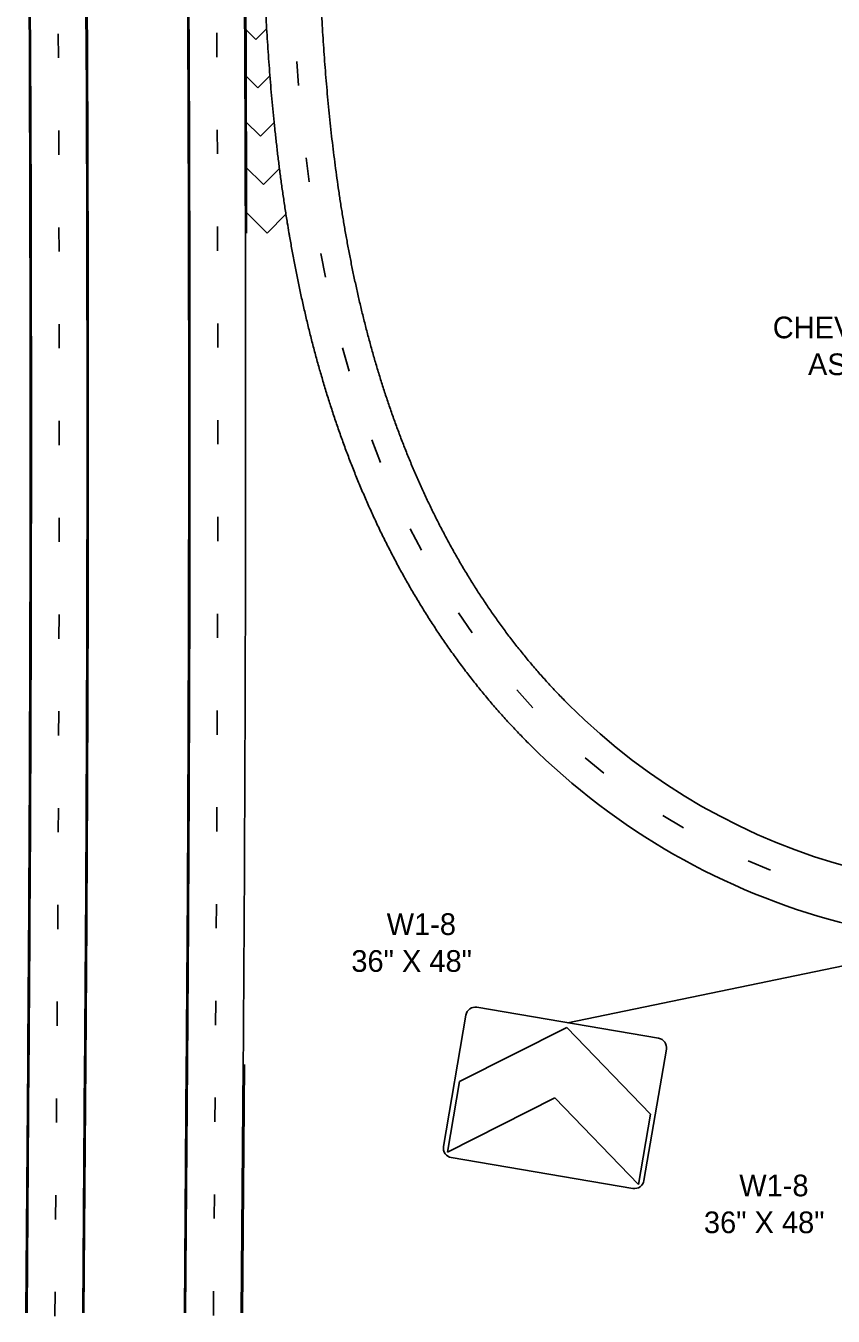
# Model space of a CAD drawing. Extents: x 582908 to 586040, y 1530940 to 1532988.
# Drawn here: x 584487 to 585009, y 1531179 to 1532013 of the extents above; entities that cross this region are included whole.
import ezdxf

# ---------------------------------------------------------------- set-up
doc = ezdxf.new("R2010")
doc.units = 0
for name, color, linetype in [('LeaderLine_dp', 7, 'Continuous'), ('NonPlottingEle_dp', 7, 'Continuous'), ('PavtMisc_ep', 7, 'Continuous'), ('PMStripe18W', 7, 'Continuous'), ('PMStripe6W', 7, 'Continuous'), ('PMStripe6W(10-30)', 7, 'Continuous'), ('PMStripe6Y', 7, 'Continuous'), ('PMStripe8W', 7, 'Continuous'), ('SignPanel', 7, 'Continuous'), ('TextLabel', 7, 'Continuous')]:
    doc.layers.add(name, color=color, linetype=linetype)

msp = doc.modelspace()

# ---------------------------------------------------------------- linework, layer by layer
at = {"layer": 'LeaderLine_dp'}
msp.add_line((585049.11, 1531412.72), (584837.21, 1531368.99), dxfattribs=at)
at = {"layer": 'NonPlottingEle_dp'}
for p, q in [((584488.37, 1532305.68), (584489.76, 1531989.04)), ((584628.22, 1532306.3), (584629.61, 1531989.65)), ((584488.69, 1531343.06), (584487.46, 1531181.72)), ((584628.53, 1531341.99), (584627.3, 1531181.72))]:
    msp.add_line(p, q, dxfattribs=at)
for radius, start in [(53646.05, 359.560511), (53785.89, 0.132453)]:
    msp.add_arc((530844.22, 1531754.55), radius, start, 0.250444, dxfattribs=at)
at = {"layer": 'PavtMisc_ep'}
for p, q in [((584525.87, 1532305.84), (584527.26, 1531989.2)), ((584590.72, 1532306.13), (584592.11, 1531989.49)), ((584526.19, 1531342.77), (584524.96, 1531181.72)), ((584591.03, 1531342.27), (584589.8, 1531181.72))]:
    msp.add_line(p, q, dxfattribs=at)
for radius in [53683.55, 53748.39]:
    msp.add_arc((530844.22, 1531754.55), radius, 359.560511, 0.250444, dxfattribs=at)
at = {"layer": 'PMStripe18W'}
for p, q in [((584636, 1532003.89), (584628.69, 1532011.14)), ((584636, 1532003.89), (584642.84, 1532010.8)), ((584637.26, 1531972.65), (584628.82, 1531981.01)), ((584637.26, 1531972.65), (584645.01, 1531980.47)), ((584638.85, 1531941.4), (584628.97, 1531951.2)), ((584638.85, 1531941.4), (584647.77, 1531950.4)), ((584640.83, 1531910.16), (584629.07, 1531921.82)), ((584640.83, 1531910.16), (584651.2, 1531920.62)), ((584643.25, 1531878.92), (584629.16, 1531892.9)), ((584643.25, 1531878.92), (584655.34, 1531891.12))]:
    msp.add_line(p, q, dxfattribs=at)
at = {"layer": 'PMStripe6W'}
for p, q in [((584489.16, 1532305.68), (584490.54, 1531989.04)), ((584489.47, 1531343.05), (584488.24, 1531181.72)), ((584627.75, 1531341.99), (584626.52, 1531181.72))]:
    msp.add_line(p, q, dxfattribs=at)
for centre, radius, start, end in [((585125.59, 1531862.24), 407.03, 225.07112, 46.1803), ((530844.22, 1531754.55), 53646.83, 359.560511, 0.250444), ((530844.22, 1531754.55), 53785.11, 359.560511, 0.132453)]:
    msp.add_arc(centre, radius, start, end, dxfattribs=at)
msp.add_spline([(584674.06, 1532160.86), (584674.21, 1532152.42), (584674.36, 1532143.97), (584674.51, 1532135.53), (584674.67, 1532127.08), (584674.84, 1532118.64), (584675.03, 1532110.19), (584675.22, 1532101.75), (584675.44, 1532093.3), (584675.67, 1532084.86), (584675.93, 1532076.41), (584676.2, 1532067.97), (584676.51, 1532059.52), (584676.84, 1532051.08), (584677.2, 1532042.64), (584677.6, 1532034.2), (584678.03, 1532025.76), (584678.5, 1532017.33), (584679.01, 1532008.89), (584679.57, 1532000.46), (584680.16, 1531992.03), (584680.81, 1531983.61), (584681.5, 1531975.18), (584682.25, 1531966.77), (584683.05, 1531958.35), (584683.91, 1531949.95), (584684.83, 1531941.54), (584685.81, 1531933.15), (584686.85, 1531924.76), (584687.96, 1531916.38), (584689.14, 1531908.01), (584690.38, 1531899.65), (584691.7, 1531891.3), (584693.1, 1531882.97), (584694.57, 1531874.64), (584696.12, 1531866.33), (584697.76, 1531858.04), (584699.47, 1531849.76), (584701.28, 1531841.5), (584703.17, 1531833.26), (584705.15, 1531825.04), (584707.22, 1531816.85), (584709.39, 1531808.67), (584711.66, 1531800.53), (584714.02, 1531792.41), (584716.48, 1531784.32), (584719.05, 1531776.26), (584721.72, 1531768.24), (584724.49, 1531760.25), (584727.37, 1531752.3), (584730.37, 1531744.39), (584733.47, 1531736.52), (584736.68, 1531728.7), (584740.01, 1531720.93), (584743.46, 1531713.2), (584747.02, 1531705.53), (584750.7, 1531697.91), (584754.5, 1531690.36), (584758.42, 1531682.86), (584762.46, 1531675.43), (584766.63, 1531668.07), (584770.91, 1531660.78), (584775.33, 1531653.56), (584779.86, 1531646.42), (584784.53, 1531639.36), (584789.32, 1531632.39), (584794.23, 1531625.5), (584799.28, 1531618.71), (584804.45, 1531612.01), (584809.74, 1531605.42), (584815.17, 1531598.92), (584820.72, 1531592.54), (584826.4, 1531586.26), (584832.2, 1531580.1), (584838.12, 1531574.07)], degree=3, dxfattribs=at)
at = {"layer": 'PMStripe6W(10-30)'}
for p, q in [((584508.43, 1532007.6), (584508.5, 1531991.98)), ((584610.78, 1532008.11), (584610.84, 1531992.49)), ((584662.32, 1531989.69), (584663.56, 1531974.11)), ((584611.03, 1531945.61), (584611.08, 1531929.99)), ((584508.68, 1531945.1), (584508.74, 1531929.48)), ((584668.4, 1531927.49), (584670.42, 1531912)), ((584508.87, 1531882.6), (584508.9, 1531866.98)), ((584611.21, 1531883.11), (584611.25, 1531867.49)), ((584677.94, 1531865.73), (584680.98, 1531850.41)), ((584611.32, 1531820.61), (584611.34, 1531804.99)), ((584508.98, 1531820.1), (584509, 1531804.48)), ((584691.82, 1531804.81), (584696.06, 1531789.77)), ((584509.02, 1531757.6), (584509.02, 1531741.98)), ((584611.36, 1531758.11), (584611.36, 1531742.49)), ((584710.81, 1531745.29), (584716.44, 1531730.71)), ((584611.33, 1531695.61), (584611.31, 1531679.99)), ((584508.99, 1531695.1), (584508.97, 1531679.48)), ((584735.59, 1531687.94), (584742.75, 1531674.06)), ((584508.88, 1531632.6), (584508.84, 1531616.98)), ((584611.23, 1531633.11), (584611.19, 1531617.49)), ((584766.67, 1531633.76), (584775.46, 1531620.85)), ((584804.34, 1531583.95), (584814.8, 1531572.34)), ((584611.05, 1531570.62), (584610.99, 1531554.99)), ((584508.7, 1531570.1), (584508.65, 1531554.48)), ((584848.47, 1531540.01), (584860.5, 1531530.04)), ((584508.45, 1531507.6), (584508.38, 1531491.98)), ((584610.8, 1531508.12), (584610.73, 1531492.49)), ((584898.67, 1531502.88), (584912.03, 1531494.79)), ((584953.78, 1531473.51), (584968.18, 1531467.46)), ((584610.48, 1531445.62), (584610.38, 1531429.99)), ((584508.13, 1531445.1), (584508.04, 1531429.48)), ((584507.73, 1531382.6), (584507.62, 1531366.98)), ((584610.08, 1531383.12), (584609.97, 1531367.49)), ((584609.62, 1531320.62), (584609.5, 1531305)), ((584507.27, 1531320.11), (584507.15, 1531304.48)), ((584506.79, 1531257.61), (584506.67, 1531241.98)), ((584609.14, 1531258.12), (584609.02, 1531242.5)), ((584608.66, 1531195.62), (584608.54, 1531180)), ((584506.31, 1531195.11), (584506.19, 1531179.48))]:
    msp.add_line(p, q, dxfattribs=at)
at = {"layer": 'PMStripe6Y'}
for p, q in [((584525.09, 1532305.84), (584526.48, 1531989.2)), ((584591.5, 1532306.13), (584592.89, 1531989.49)), ((584525.41, 1531342.78), (584524.17, 1531181.72)), ((584591.81, 1531342.27), (584590.58, 1531181.72))]:
    msp.add_line(p, q, dxfattribs=at)
for centre, radius, start, end in [((585125.59, 1531862.24), 442.97, 225.02103, 46.23038), ((530844.22, 1531754.55), 53682.77, 359.560511, 0.250444), ((530844.22, 1531754.55), 53749.17, 359.560511, 0.250444)]:
    msp.add_arc(centre, radius, start, end, dxfattribs=at)
msp.add_spline([(584657.3, 1531879.08), (584657.68, 1531876.87), (584659.21, 1531868.21), (584660.83, 1531859.56), (584662.53, 1531850.92), (584664.32, 1531842.28), (584666.21, 1531833.65), (584668.19, 1531825.03), (584670.26, 1531816.42), (584672.43, 1531807.83), (584674.71, 1531799.25), (584677.09, 1531790.69), (584679.58, 1531782.15), (584682.17, 1531773.63), (584684.87, 1531765.14), (584687.69, 1531756.67), (584690.62, 1531748.23), (584693.67, 1531739.82), (584696.84, 1531731.44), (584700.13, 1531723.1), (584703.55, 1531714.8), (584707.08, 1531706.53), (584710.75, 1531698.32), (584714.54, 1531690.15), (584718.46, 1531682.03), (584722.52, 1531673.96), (584726.71, 1531665.95), (584731.03, 1531658), (584735.49, 1531650.11), (584740.09, 1531642.29), (584744.83, 1531634.55), (584749.7, 1531626.88), (584754.72, 1531619.28), (584759.88, 1531611.77), (584765.18, 1531604.35), (584770.62, 1531597.02), (584776.21, 1531589.78), (584781.94, 1531582.64), (584787.81, 1531575.61), (584793.83, 1531568.69), (584799.99, 1531561.88), (584806.3, 1531555.19), (584812.48, 1531548.89)], degree=3, dxfattribs=at)
at = {"layer": 'PMStripe8W'}
msp.add_line((584627.44, 1532306.29), (584628.82, 1531989.65), dxfattribs=at)
msp.add_arc((530844.22, 1531754.55), 53785.11, 0.132453, 0.250444, dxfattribs=at)
msp.add_spline([(584638.13, 1532160.23), (584638.28, 1532151.78), (584638.43, 1532143.32), (584638.58, 1532134.85), (584638.74, 1532126.37), (584638.91, 1532117.88), (584639.1, 1532109.38), (584639.3, 1532100.87), (584639.51, 1532092.35), (584639.75, 1532083.82), (584640.01, 1532075.28), (584640.29, 1532066.73), (584640.6, 1532058.17), (584640.93, 1532049.6), (584641.3, 1532041.03), (584641.71, 1532032.44), (584642.15, 1532023.84), (584642.63, 1532015.24), (584643.15, 1532006.63), (584643.71, 1531998.01), (584644.32, 1531989.39), (584644.98, 1531980.76), (584645.7, 1531972.12), (584646.47, 1531963.47), (584647.29, 1531954.82), (584648.17, 1531946.17), (584649.12, 1531937.51), (584650.13, 1531928.85), (584651.2, 1531920.19), (584652.35, 1531911.52), (584653.57, 1531902.86), (584654.86, 1531894.19), (584656.23, 1531885.53), (584657.3, 1531879.08)], degree=3, dxfattribs=at)
at = {"layer": 'SignPanel'}
for p, q in [((584767.29, 1531330.96), (584836.69, 1531365.96)), ((584836.69, 1531365.96), (584890.62, 1531309.98)), ((584759.55, 1531285.47), (584767.29, 1531330.96)), ((584828.95, 1531320.47), (584759.55, 1531285.47)), ((584882.88, 1531264.49), (584828.95, 1531320.47)), ((584890.62, 1531309.98), (584882.88, 1531264.49))]:
    msp.add_line(p, q, dxfattribs=at)
for points in [[(584778.58, 1531378.96), (584895.84, 1531359.01)], [(584757.04, 1531289.02), (584771.48, 1531373.93)], [(584900.87, 1531351.92), (584886.43, 1531267)], [(584879.33, 1531261.97), (584762.07, 1531281.92)]]:
    msp.add_lwpolyline(points, dxfattribs=at)
for centre, start, end in [((584777.55, 1531372.9), 80.34482, 170.34482), ((584894.81, 1531352.95), 350.34482, 80.34482), ((584763.1, 1531287.98), 170.34482, 260.34482), ((584880.36, 1531268.04), 260.34482, 350.34482)]:
    msp.add_arc(centre, 6.15, start, end, dxfattribs=at)

# ---------------------------------------------------------------- texts
at = {"layer": 'TextLabel'}
for s, p in [('CHEVRON SIGNS ON AN', (584969.57, 1531810.96)), ('AS-NEEDED BASIS', (584992.3, 1531787.16)), ('W1-8', (584720.37, 1531425.65)), ('36" X 48"', (584697.56, 1531401.85)), ('W1-8', (584947.94, 1531256.9)), ('36" X 48"', (584925.13, 1531233.1))]:
    msp.add_text(s, height=14, dxfattribs=at).set_placement(p)

doc.saveas('drawing.dxf')
